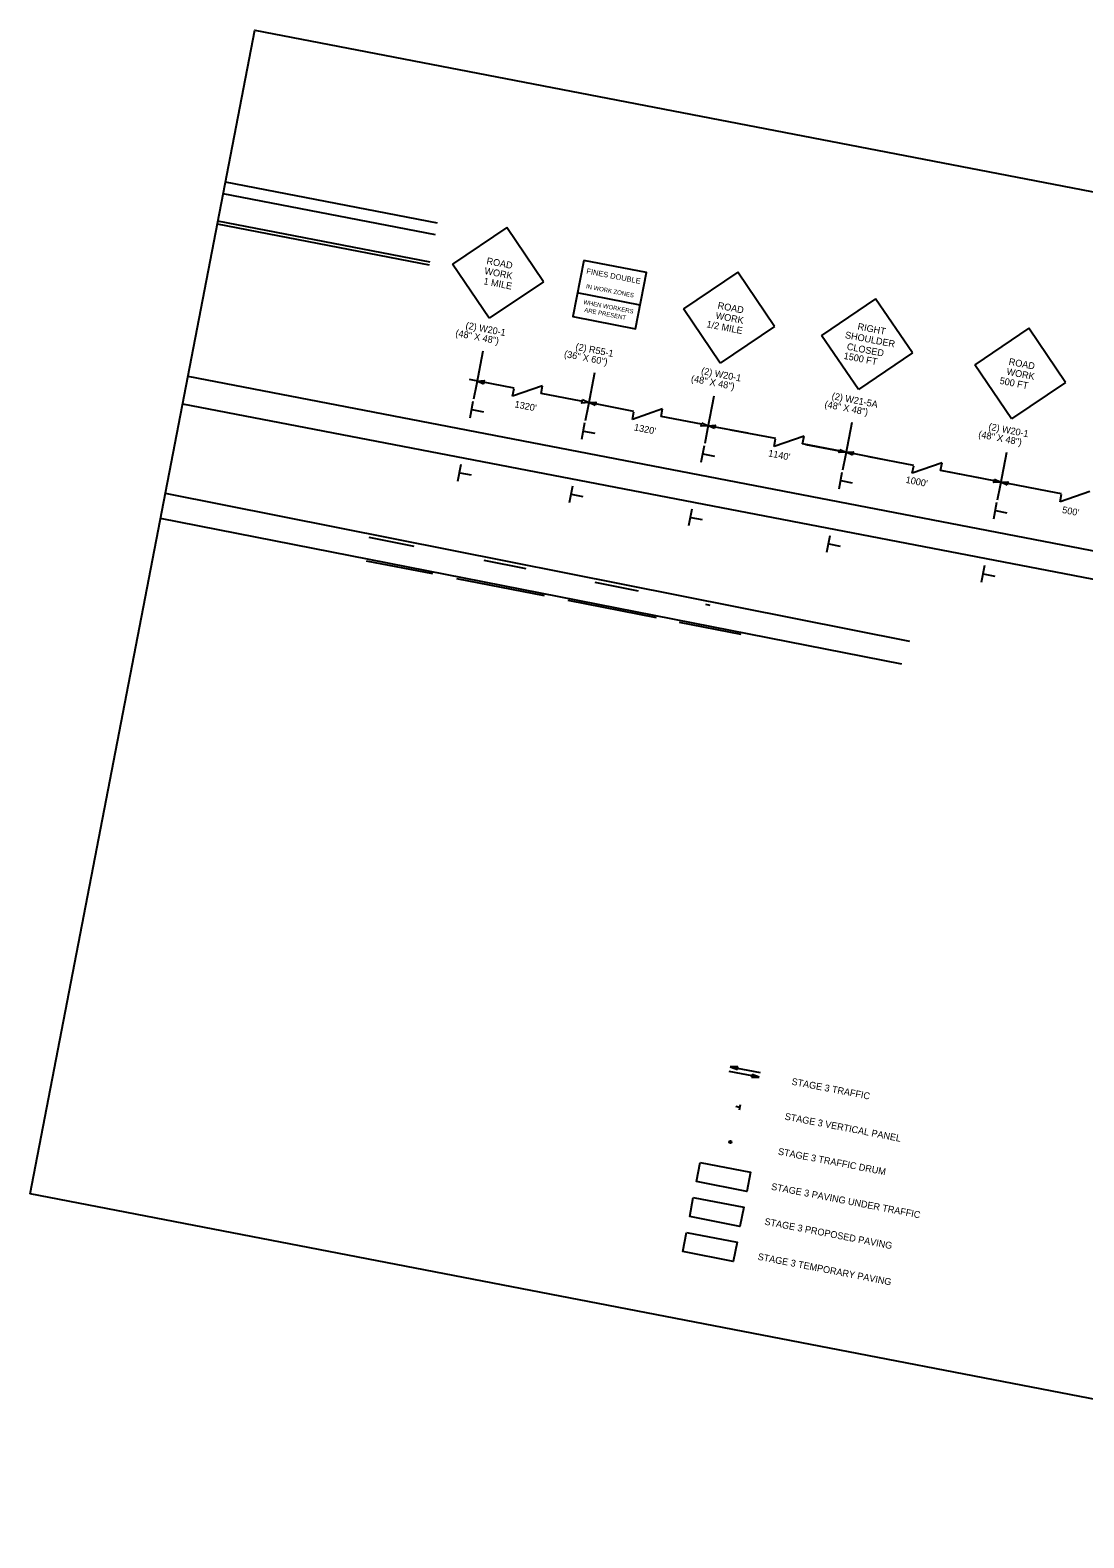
# Model space of a CAD drawing. Extents: x 605560 to 609391, y 416008 to 420725.
# Drawn here: x 605560 to 606487, y 419400 to 420725 of the extents above; entities that cross this region are included whole.
import ezdxf

# ---------------------------------------------------------------- set-up
doc = ezdxf.new("R2010")
doc.units = 0
for name, color, linetype in [('G-No Plot-Border-1', 7, 'Continuous'), ('Level 3', 7, 'Continuous'), ('Level 47', 7, 'Continuous'), ('Level 62', 7, 'Continuous'), ('R_Draft', 7, 'Continuous'), ('S_EDGE_PAVEMENT', 7, 'Continuous'), ('S_SHOULDER', 7, 'Continuous'), ('Stage 2B_Sign', 7, 'Continuous')]:
    doc.layers.add(name, color=color, linetype=linetype)

msp = doc.modelspace()

# ---------------------------------------------------------------- linework, layer by layer
at = {"layer": 'G-No Plot-Border-1'}
msp.add_lwpolyline([(605560.5, 419701.9), (605758, 420725.3), (606934.3, 420498.3), (606934.3, 420498.3), (606934.3, 420498.3), (607014.8, 420482.7), (607005.4, 420434.1), (607119.6, 420412), (607315.1, 420374.3), (607315.1, 420374.3), (607284.2, 420214.2), (607284.2, 420214.2), (607126.9, 419399.5)], close=True, dxfattribs=at)
at = {"layer": 'Level 3'}
for p, q in [((606184.1, 419778), (606180.8, 419778.7)), ((606184.7, 419780.4), (606183.7, 419775.5))]:
    msp.add_line(p, q, dxfattribs=at)
at = {"layer": 'Level 47'}
msp.add_circle((606176.1, 419747.7), 1, dxfattribs=at)
at = {"layer": 'Level 62'}
for p, q in [((606201.5, 419804.5), (606175.1, 419809.6)), ((606182.7, 419813.7), (606175.9, 419813.8)), ((606175.9, 419813.8), (606182.3, 419811.4)), ((606175.9, 419813.8), (606202.3, 419808.7)), ((606177.6, 419813.3), (606182.4, 419811.9)), ((606182.6, 419813.1), (606177.7, 419813.6)), ((606182.3, 419811.4), (606182.7, 419813.7)), ((606195.1, 419806.9), (606194.7, 419804.6)), ((606194.7, 419804.6), (606201.5, 419804.5)), ((606194.8, 419805.2), (606199.7, 419804.6)), ((606199.8, 419804.9), (606195, 419806.3)), ((606201.5, 419804.5), (606195.1, 419806.9))]:
    msp.add_line(p, q, dxfattribs=at)
at = {"layer": 'R_Draft'}
for p, q in [((605958.4, 420442.9), (605952.8, 420413.8)), ((605986, 420410.4), (605946.6, 420418.1)), ((605952.8, 420413.8), (605950.3, 420400.9)), ((606010.9, 420412.6), (605984.6, 420403.4)), ((606009.6, 420405.9), (606010.9, 420412.6)), ((606056.6, 420423.9), (606051, 420394.8)), ((605984.6, 420403.4), (605985.9, 420410.1)), ((606044.8, 420399.1), (606009.6, 420405.9)), ((606161.6, 420403.6), (606156, 420374.6)), ((606051, 420394.8), (606048.5, 420381.9)), ((606091.3, 420390.1), (606051.6, 420397.8)), ((606116.5, 420392.3), (606090, 420383)), ((606090, 420383), (606091.3, 420389.8)), ((606115.2, 420385.5), (606116.5, 420392.3)), ((606150.7, 420378.7), (606115.2, 420385.5)), ((606156, 420374.6), (606153.5, 420361.7)), ((606191.3, 420370.8), (606156.6, 420377.5)), ((606215.9, 420366.1), (606176.5, 420373.7)), ((606282.8, 420380.2), (606277.2, 420351.2)), ((606240.8, 420368.2), (606214.5, 420359.1)), ((606214.5, 420359.1), (606215.8, 420365.8)), ((606239.5, 420361.5), (606240.8, 420368.2)), ((606274.7, 420354.7), (606239.5, 420361.5)), ((606242.1, 420361), (606277.8, 420354.1)), ((606277.2, 420351.2), (606274.7, 420338.3)), ((606313, 420347.3), (606277.8, 420354.1)), ((606337.3, 420342.6), (606297.9, 420350.2)), ((606418.8, 420354), (606413.2, 420324.9)), ((606362.2, 420344.8), (606336, 420335.6)), ((606336, 420335.6), (606337.3, 420342.3)), ((606360.9, 420338.1), (606362.2, 420344.8)), ((606396.1, 420331.3), (606360.9, 420338.1)), ((606456.4, 420319.6), (606362.5, 420337.8)), ((606413.2, 420324.9), (606410.7, 420312)), ((606413.2, 420324.9), (606410.7, 420312)), ((606467.3, 420317.5), (606456.4, 420319.6)), ((606492.2, 420319.7), (606466, 420310.5)), ((606466, 420310.5), (606467.2, 420317.2))]:
    msp.add_line(p, q, dxfattribs=at)
for points in [[(605959, 420414.1), (605953.4, 420416.7), (605959.6, 420417.1)], [(606046, 420400.4), (606051.6, 420397.8), (606045.4, 420397.4)], [(606057.2, 420395.2), (606051.6, 420397.8), (606057.8, 420398.1)], [(606151, 420380.1), (606156.6, 420377.5), (606150.4, 420377.2)], [(606162.2, 420374.9), (606156.6, 420377.5), (606162.7, 420377.9)], [(606272.2, 420356.7), (606277.8, 420354.1), (606271.6, 420353.8)], [(606283.4, 420351.5), (606277.8, 420354.1), (606284, 420354.5)], [(606408.2, 420330.5), (606413.8, 420327.9), (606407.6, 420327.5)], [(606419.4, 420325.3), (606413.8, 420327.9), (606420, 420328.2)], [(606149.5, 419729.7), (606193.8, 419721.2), (606190.5, 419704.2), (606146.2, 419712.8)], [(606149.5, 419729.7), (606193.8, 419721.2), (606190.5, 419704.2), (606146.2, 419712.8)], [(606149.5, 419729.7), (606193.8, 419721.2), (606190.5, 419704.2), (606146.2, 419712.8)], [(606143.5, 419698.9), (606187.8, 419690.4), (606184.5, 419673.4), (606140.3, 419682)], [(606137.6, 419668.1), (606181.9, 419659.6), (606178.6, 419642.6), (606134.3, 419651.2)]]:
    msp.add_lwpolyline(points, close=True, dxfattribs=at)
at = {"layer": 'S_EDGE_PAVEMENT'}
for p, q in [((605916.8, 420545.3), (605730.2, 420581.3)), ((605912.1, 420521.4), (605725.6, 420557.4)), ((606677.7, 420232), (605699.3, 420420.8)), ((606673.1, 420208.2), (605694.6, 420396.5)), ((606333.9, 420187.6), (605679.4, 420317.8)), ((606326.8, 420167.9), (605675.1, 420295.8)), ((605898, 420271.3), (605858.5, 420279.1)), ((605914.4, 420247.1), (605856.3, 420258.5)), ((605996.6, 420251.6), (605959.5, 420259)), ((606012.8, 420227.8), (605935.7, 420242.9)), ((606095.3, 420232), (606057.1, 420239.6)), ((606111.2, 420208.4), (606033.5, 420223.7)), ((606158.3, 420219.5), (606154.6, 420220.2)), ((606185.6, 420193.9), (606131.3, 420204.5))]:
    msp.add_line(p, q, dxfattribs=at)
at = {"layer": 'S_SHOULDER'}
for p, q in [((605918.7, 420555.6), (605732.2, 420591.6)), ((605911.6, 420518.7), (605725.1, 420554.7))]:
    msp.add_line(p, q, dxfattribs=at)
at = {"layer": 'Stage 2B_Sign'}
for p, q in [((605979.5, 420551.7), (605931.8, 420519.5)), ((606011.7, 420504.1), (605979.5, 420551.7)), ((605964, 420471.9), (605931.8, 420519.5)), ((606011.7, 420504.1), (605964, 420471.9)), ((606182.6, 420512.5), (606135, 420480.3)), ((606214.9, 420464.8), (606182.6, 420512.5)), ((606096.8, 420483.5), (606041.5, 420494.2)), ((606167.2, 420432.6), (606135, 420480.3)), ((606303.8, 420489.1), (606256.3, 420456.8)), ((606336.2, 420441.5), (606303.8, 420489.1)), ((606214.9, 420464.8), (606167.2, 420432.6)), ((606288.6, 420409.2), (606256.3, 420456.8)), ((606438.5, 420463.2), (606390.9, 420431)), ((606470.7, 420415.6), (606438.5, 420463.2)), ((606336.2, 420441.5), (606288.6, 420409.2)), ((606423.1, 420383.4), (606390.9, 420431)), ((606470.7, 420415.6), (606423.1, 420383.4)), ((605947.2, 420384.5), (605950, 420399.2)), ((605948.8, 420391.8), (605958.9, 420389.8)), ((606045.4, 420365.5), (606048.2, 420380.3)), ((606047, 420372.8), (606057, 420370.9)), ((606150.3, 420345.3), (606153.2, 420360)), ((606152, 420352.6), (606162, 420350.6)), ((605936.4, 420328.8), (605939.3, 420343.6)), ((605938.1, 420336.1), (605948.1, 420334.2)), ((606271.6, 420321.9), (606274.4, 420336.6)), ((606034.6, 420309.9), (606037.5, 420324.6)), ((606273.2, 420329.2), (606283.2, 420327.2)), ((606036.2, 420317.2), (606046.3, 420315.2)), ((606407.6, 420295.6), (606410.4, 420310.3)), ((606139.6, 420289.6), (606142.4, 420304.4)), ((606141.2, 420296.9), (606151.3, 420295)), ((606409.2, 420302.9), (606419.2, 420301)), ((606260.8, 420266.2), (606263.7, 420281)), ((606262.5, 420273.5), (606272.5, 420271.6)), ((606396.8, 420240), (606399.7, 420254.7)), ((606398.4, 420247.3), (606408.5, 420245.3))]:
    msp.add_line(p, q, dxfattribs=at)
msp.add_lwpolyline([(606047.1, 420522.8), (606037.5, 420473.5), (606092.8, 420462.8), (606102.3, 420512.2)], close=True, dxfattribs=at)

# ---------------------------------------------------------------- texts
at = {"layer": 'R_Draft'}
for s, rotation, p in [('(2) W20-1', 349.0745, (605942.9, 420463)), ('(48" X 48")', 349.0745, (605934, 420456.3)), ('(36" X 60")', 349.0745, (606029.5, 420437.9)), ('(2) R55-1', 349.0745, (606039.5, 420444.3)), ('(2) W20-1', 349.0745, (606150, 420423)), ('(48" X 48")', 349.0745, (606141.1, 420416.3)), ("1320'", 349.086, (605986, 420393.7)), ('(48" X 48")', 349.0745, (606258.5, 420393.7)), ('(2) W21-5A', 349.0745, (606264.8, 420400.9)), ("1320'", 349.086, (606091, 420373.4)), ("1140'", 349.086, (606209, 420350.6)), ("1000'", 349.086, (606329.8, 420327.3)), ("500'", 349.086, (606467.4, 420300.8)), ('STAGE 3 TRAFFIC', 349.0745, (606229.5, 419798.1)), ('STAGE 3 VERTICAL PANEL', 349.0745, (606223.5, 419767.4)), ('STAGE 3 TRAFFIC DRUM', 349.0745, (606217.6, 419736.6)), ('STAGE 3 PAVING UNDER TRAFFIC', 349.0745, (606211.6, 419705.7)), ('STAGE 3 PROPOSED PAVING', 349.0745, (606205.7, 419675)), ('STAGE 3 TEMPORARY PAVING', 349.0745, (606199.7, 419644.1))]:
    msp.add_text(s, height=6, rotation=rotation, dxfattribs=at).set_placement(p)
at = {"layer": 'Stage 2B_Sign'}
for s, height, rotation, p in [('ROAD', 5.99, 349.075, (605961.3, 420519.7)), ('1 MILE', 5.99, 349.0751, (605958.7, 420501.9)), ('WORK', 5.99, 349.0745, (605959.5, 420510.9)), ('FINES DOUBLE', 4.776, 349.0745, (606049.2, 420511.3)), ('IN WORK ZONES', 3.82, 349.0745, (606048.9, 420498.3)), ('WHEN WORKERS', 3.821, 349.0745, (606046.5, 420484.5)), ('ARE PRESENT', 3.821, 349.0745, (606047.4, 420477.5)), ('WORK', 5.99, 349.0745, (606162.7, 420471.7)), ('ROAD', 5.99, 349.075, (606164.5, 420480.5)), ('1/2 MILE', 5.99, 349.0751, (606154.7, 420464.1)), ('RIGHT', 5.99, 349.175, (606287.5, 420462)), ('SHOULDER', 5.99, 349.1748, (606276.5, 420454.6)), ('1500 FT', 5.99, 349.174, (606275.3, 420436.3)), ('CLOSED', 5.99, 349.174, (606278.1, 420444.4)), ('WORK', 5.99, 349.0735, (606418.5, 420422.4)), ('ROAD', 5.99, 349.0739, (606420.4, 420431.2)), ('500 FT', 5.99, 349.074, (606412.4, 420414.4)), ('(48" X 48")', 6, 349.0745, (606393.7, 420367.3)), ('(2) W20-1', 6, 349.0745, (606402.6, 420374))]:
    msp.add_text(s, height=height, rotation=rotation, dxfattribs=at).set_placement(p)

doc.saveas('drawing.dxf')
